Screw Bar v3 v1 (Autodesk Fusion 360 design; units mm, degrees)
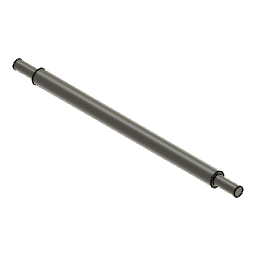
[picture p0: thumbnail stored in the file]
sketch "Sketch1" plane through (0, 0, 0) normal (0, 1, 0) x axis (1, 0, 0)
  line L1 (0, 3) -> (-42.0001, 3)
  line L2 (42, 2) -> (52, 2)
  line L3 (61.7409, 0) -> (-72.0348, 0)
  line L4 (42.0001, 3) -> (42, 2)
  line L5 (52, 2) -> (52, 0)
  line L6 (-42.0001, 3) -> (-42, 2)
  line L7 (-42, 2) -> (-52, 2)
  line L8 (0, 11.8071) -> (0, -14.9062)
  line L9 (52, 0) -> (-52, 0)
  line L10 (-52, 2) -> (-52, 0)
  line L11 (0, 3) -> (42.0001, 3)
  point P8 (-52, 0)
  point P11 (0, 3)
  point P4 (0, 0)
  point P16 (52, 0)
  point P9 (-52, 2)
  point P15 (52, 2)
  point P3 (-42, 2)
  point P14 (42, 2)
  point P10 (-42.0001, 3)
  point P12 (42.0001, 3)
  point P13 (0, 3)
  horizontal L3
  perpendicular L3 L8
  coincident P8 L3
  coincident P11 L8
  perpendicular L1 L8
  coincident P4 L3
  coincident P4 L8
  symmetric P8 P16 L8
  symmetric P9 P15 L8
  symmetric P3 P14 L8
  symmetric P10 P12 L8
  symmetric P11 P13 L8
  perpendicular L5 L9
  dimension "d1" distance P8 P9 = 2
  dimension "d2" distance P3 P9 = 10
  dimension "d3" distance P3 P10 = 1
  dimension "d4" distance P11 L10 = 52
  dimension "d5" distance L1 L3 = 3
revolve "Revolve1" sketch "Sketch1" AlongAngle 360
